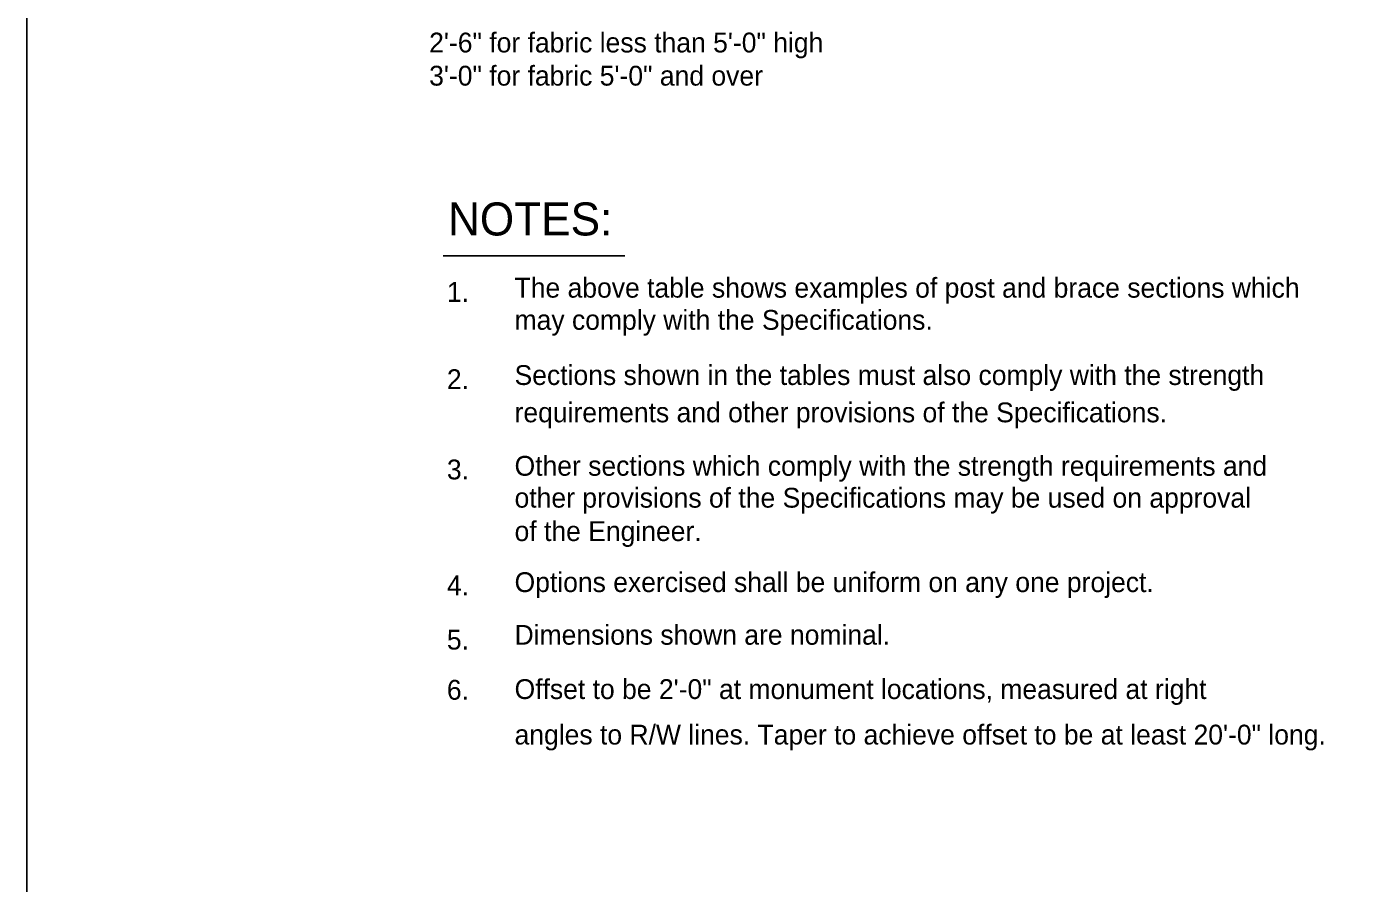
# Model space of a CAD drawing. Extents: x 6710407 to 6714861, y 1868090 to 1871317.
# Drawn here: x 6711433.8 to 6711838.5, y 1869988 to 1870247.4 of the extents above; entities that cross this region are included whole.
import ezdxf

# ---------------------------------------------------------------- set-up
doc = ezdxf.new("R2010")
doc.units = 0
doc.layers.add('G-TTLB-VIEW', color=7, linetype='Continuous')
doc.layers.add('Nongeo Data(60)', color=7, linetype='Continuous')

msp = doc.modelspace()

# ---------------------------------------------------------------- linework, layer by layer
at = {"layer": 'G-TTLB-VIEW'}
msp.add_lwpolyline([(6711433.78, 1870605.06), (6713227.53, 1870605.06), (6713227.53, 1869155.06), (6711433.78, 1869155.06)], close=True, dxfattribs=at)
at = {"layer": 'Nongeo Data(60)'}
msp.add_line((6711559.92, 1870178.01), (6711614.93, 1870178.01), dxfattribs=at)

# ---------------------------------------------------------------- texts
for s, height, p in [('2\'-6" for fabric less than 5\'-0" high', 6, (6711555.64, 1870239.6)), ('3\'-0" for fabric 5\'-0" and over', 6, (6711555.64, 1870229.56)), ('NOTES:', 10, (6711561.33, 1870184.17)), ('The above table shows examples of post and brace sections which ', 6, (6711581.5, 1870165.34)), ('1.', 6, (6711561.01, 1870164.06)), ('may comply with the Specifications.', 6, (6711581.5, 1870155.61)), ('2.', 6, (6711561.01, 1870137.64)), ('Sections shown in the tables must also comply with the strength', 6, (6711581.5, 1870138.89)), ('requirements and other provisions of the Specifications.', 6, (6711581.5, 1870127.59)), ('3.', 6, (6711561.01, 1870110.3)), ('Other sections which comply with the strength requirements and', 6, (6711581.5, 1870111.4)), ('other provisions of the Specifications may be used on approval', 6, (6711581.5, 1870101.74)), ('of the Engineer.', 6, (6711581.5, 1870091.62)), ('Options exercised shall be uniform on any one project.', 6, (6711581.5, 1870076.17)), ('4.', 6, (6711561.01, 1870075.2)), ('Dimensions shown are nominal.', 6, (6711581.5, 1870060.23)), ('5.', 6, (6711561.01, 1870058.76)), ('6.', 6, (6711561.01, 1870043.57)), ('Offset to be 2\'-0" at monument locations, measured at right', 6, (6711581.5, 1870043.78)), ('angles to R/W lines. Taper to achieve offset to be at least 20\'-0" long.', 6, (6711581.5, 1870030))]:
    msp.add_text(s, height=height, dxfattribs=at).set_placement(p)

doc.saveas('drawing.dxf')
